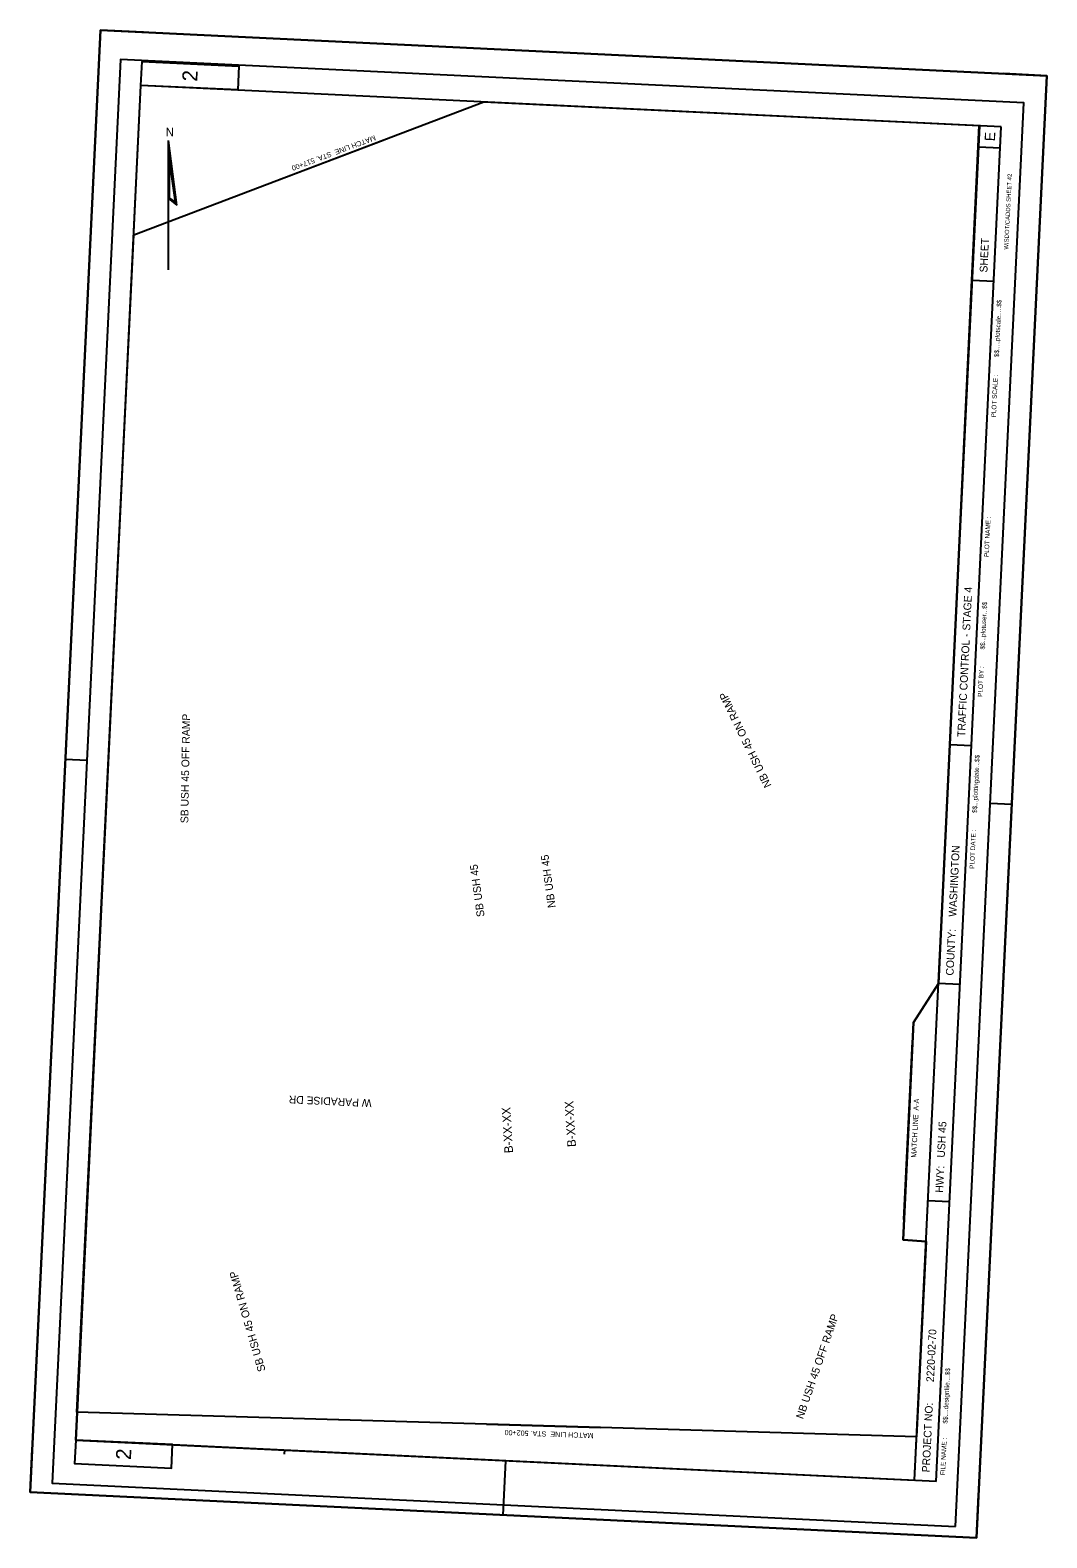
# Model space of a CAD drawing. Extents: x 359517 to 360698, y 174406 to 176157.
import ezdxf

# ---------------------------------------------------------------- set-up
doc = ezdxf.new("R2010")
doc.units = 0
for name, color, linetype in [('Default', 7, 'Continuous'), ('P_ALI_100_Equation', 7, 'Continuous'), ('P_ALI_100_PIData', 7, 'Continuous'), ('P_ALI_20', 7, 'Continuous'), ('P_ALI_200_Equation', 7, 'Continuous'), ('P_ALI_20_Sta', 7, 'Continuous'), ('P_ALI_20_Tic', 7, 'Continuous'), ('P_ALI_50_Equation', 7, 'Continuous'), ('P_ALI_50_Tic', 7, 'Continuous')]:
    doc.layers.add(name, color=color, linetype=linetype)

msp = doc.modelspace()

# ---------------------------------------------------------------- linework, layer by layer
for p, q in [((359596.5, 176107.3), (359598.9, 176157.2)), ((359648.8, 176154.8), (359598.9, 176157.2)), ((359570.1, 174519.9), (359645.8, 176093.1)), ((360644.7, 176045), (359645.8, 176093.1)), ((360697.6, 176104.3), (360647.6, 176106.7)), ((360695.2, 176054.4), (360697.6, 176104.3)), ((360544, 174473.1), (360619.7, 176046.2)), ((360569, 174471.9), (360644.7, 176045)), ((360643.5, 176020.1), (360618.5, 176021.3)), ((360636, 175865.2), (360611.1, 175866.5)), ((359556.9, 175285.7), (359559.3, 175335.6)), ((360610.1, 175325.9), (360585.1, 175327.1)), ((359558.1, 175310.7), (359583.1, 175309.5)), ((360655.6, 175232.8), (360658.1, 175282.8)), ((360656.8, 175257.8), (360631.9, 175259)), ((360596.7, 175048.7), (360571.8, 175049.9)), ((360584.6, 174796.5), (360559.6, 174797.7)), ((360071.3, 174533.4), (360071.3, 174533.4)), ((360569, 174471.9), (359570.1, 174519.9)), ((359517.1, 174459.2), (359519.5, 174509.1)), ((359812.3, 174508.3), (359812.1, 174503.3)), ((360066.5, 174432.7), (360069.5, 174495.9)), ((359567.1, 174456.8), (359517.1, 174459.2)), ((360615.9, 174406.3), (360618.3, 174456.2)), ((360091.5, 174431.5), (360041.5, 174433.9)), ((360615.9, 174406.3), (360565.9, 174408.7))]:
    msp.add_line(p, q)
for points in [[(359645.8, 176093.1), (359647.2, 176120.6), (359759.5, 176115.2), (359758.2, 176087.7)], [(359570.1, 174519.9), (359568.8, 174492.5), (359681.2, 174487.1), (359682.5, 174514.5)]]:
    msp.add_lwpolyline(points, close=True)
at = {"layer": 'Default'}
msp.add_lwpolyline([(359637.5, 175919.4), (360044, 176073.9), (360619.2, 176046.3), (360571.8, 175049.9), (360542.7, 175004.7), (360530.6, 174752.5), (360557.4, 174750.6), (360546.4, 174523.7), (360179.3, 174534.4), (359571.3, 174552.3)], close=True, dxfattribs=at)
msp.add_lwpolyline([(359637.5, 175919.4), (360044, 176073.9), (360619.2, 176046.3), (360571.8, 175049.9), (360542.7, 175004.7), (360530.6, 174752.5), (360557.4, 174750.6), (360546.4, 174523.7), (360179.3, 174534.4), (359571.3, 174552.3)], close=True, dxfattribs=at)
msp.add_lwpolyline([(359637.5, 175919.4), (360044, 176073.9), (360619.2, 176046.3), (360571.8, 175049.9), (360542.7, 175004.7), (360530.6, 174752.5), (360557.4, 174750.6), (360546.4, 174523.7), (360179.3, 174534.4), (359571.3, 174552.3)], close=True, dxfattribs=at)
at = {"layer": 'P_ALI_100_Equation'}
for p, q in [((359687.6, 175954), (359677.6, 176029)), ((359677.6, 175961.5), (359677.6, 176029)), ((359678.4, 175961.8), (359678.4, 176017.7)), ((359686.7, 175955.6), (359678.4, 176017.7)), ((359679.1, 175962.2), (359679.1, 176006.4)), ((359685.7, 175957.3), (359679.1, 176006.4)), ((359677.6, 175961.5), (359687.6, 175954)), ((359677.6, 175879), (359677.6, 175961.5)), ((359677.9, 175879), (359677.9, 175961.3)), ((359678.4, 175961.8), (359686.7, 175955.6)), ((359679.1, 175962.2), (359685.7, 175957.3))]:
    msp.add_line(p, q, dxfattribs=at)
msp.add_lwpolyline([(359677.7, 176028.9), (359677.6, 176028.9)], dxfattribs=at)
at = {"layer": 'P_ALI_20'}
for points in [[(360615.9, 174406.3), (360697.6, 176104.3), (359598.9, 176157.2), (359517.1, 174459.2)], [(360591.5, 174419.5), (360671, 176072.6), (359622.2, 176123), (359542.7, 174469.9)]]:
    msp.add_lwpolyline(points, close=True, dxfattribs=at)
at = {"layer": 'P_ALI_200_Equation'}
msp.add_lwpolyline([(359517.1, 174459.2), (359598.9, 176157.2), (360697.6, 176104.3), (360615.9, 174406.3), (359517.1, 174459.2)], dxfattribs=at)
at = {"layer": 'P_ALI_20_Sta'}
msp.add_lwpolyline([(359517.1, 174459.2), (359598.9, 176157.2), (360697.6, 176104.3), (360615.9, 174406.3)], close=True, dxfattribs=at)
at = {"layer": 'P_ALI_20_Tic'}
for p, q in [((359803.5, 175982.5), (359927.2, 176029.5)), ((360531.7, 174775.8), (360541.6, 174982.6)), ((360047, 174538.3), (360179.3, 174534.4))]:
    msp.add_line(p, q, dxfattribs=at)
at = {"layer": 'P_ALI_50_Tic'}
for points in [[(359645.3, 176092.8), (359570.1, 174519.9), (360544, 174473.4)], [(360544, 174473.4), (360557.4, 174750.6), (360530.6, 174752.5), (360542.7, 175004.7), (360571.8, 175049.9), (360619.2, 176046.3)]]:
    msp.add_lwpolyline(points, dxfattribs=at)

# ---------------------------------------------------------------- texts
for s, height, p in [('2', 17.5, (359711.1, 176097.2)), ('E', 12, (360637.3, 176028)), ('WISDOT/CADDS SHEET 42', 5, (360652.8, 175902.2)), ('SHEET ', 9, (360628.5, 175875.6)), ('$$.....plotscale.....$$', 5.4, (360641.8, 175777.4)), ('PLOT SCALE : ', 5.4, (360638.4, 175707.3)), ('PLOT NAME :                      ', 5.4, (360630.1, 175545.2)), ('TRAFFIC CONTROL - STAGE 4', 9, (360602.6, 175336.2)), ('$$...plotuser...$$', 5.4, (360625.5, 175437.8)), ('PLOT BY :', 5.4, (360622.8, 175382.8)), ('$$...plottingdate...$$', 5.4, (360616.3, 175248)), ('PLOT DATE :', 5.4, (360613.2, 175183.1)), (' WASHINGTON', 9, (360592.3, 175124)), ('COUNTY:', 9, (360589.2, 175059.1)), (' USH 45', 9, (360578.9, 174844.3)), ('HWY:', 9, (360577.1, 174806.9)), (' 2220-02-70', 9, (360566.3, 174583.6)), ('$$....designfile....$$', 5.4, (360582.2, 174538.8)), ('PROJECT NO:', 9, (360561.5, 174482.2)), ('FILE NAME :', 5.4, (360579.3, 174478.9)), ('2', 17.5, (359634.1, 174496.5))]:
    msp.add_text(s, height=height, rotation=87.2447).set_placement(p)
at = {"layer": 'P_ALI_100_Equation'}
msp.add_text('N', height=10, dxfattribs=at).set_placement((359674.5, 176033.9))
at = {"layer": 'P_ALI_100_PIData'}
for p in [(360077.9, 174853.3), (360150.9, 174860.5)]:
    msp.add_text('B-XX-XX', height=10, rotation=93.4976, dxfattribs=at).set_placement(p)
at = {"layer": 'P_ALI_50_Equation'}
for s, height, rotation, p in [('MATCH LINE  STA. 517+00', 6, 200.4031, (359917, 176035.4)), ('NB USH 45 ON RAMP', 9, 115.945, (360378.1, 175280.1)), ('SB USH 45 OFF RAMP', 9, 89.0291, (359700.7, 175236.2)), ('NB USH 45', 9, 97.7972, (360127.3, 175138.5)), ('SB USH 45', 9, 97.7972, (360044.8, 175128)), ('W PARADISE DR', 9, 177.2646, (359913.8, 174915.4)), ('MATCH LINE  A-A', 6, 87.2707, (360546, 174847.7)), ('SB USH 45 ON RAMP', 9, 106.0963, (359790.6, 174600.7)), ('NB USH 45 OFF RAMP', 9, 70.9845, (360414.5, 174543.6)), ('MATCH LINE  STA. 502+00', 6, 177.9165, (360171.4, 174527.9))]:
    msp.add_text(s, height=height, rotation=rotation, dxfattribs=at).set_placement(p)

doc.saveas('drawing.dxf')
